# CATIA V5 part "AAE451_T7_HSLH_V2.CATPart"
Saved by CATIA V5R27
Part number: HSLH
Bounding box of the stored display mesh (mm): x -160.298 to 13.7, y -18.483 to 4.512, z -115 to 125
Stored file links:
  W:\AAE 451\AAE451_T7_TailAssembly_V2\AAE451_T7_HSLH_V2.CATPart
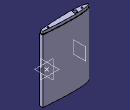
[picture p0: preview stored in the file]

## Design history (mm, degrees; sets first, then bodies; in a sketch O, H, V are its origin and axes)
Set1 "GeometryFromExcel"
  Point1: (1, 0.001, 0)
  Point2: (0.95, 0.0067, 0)
  Point3: (0.9, 0.0121, 0)
  Point4: (0.8, 0.0219, 0)
  Point5: (0.7, 0.0305, 0)
  Point6: (0.6, 0.038, 0)
  Point7: (0.5, 0.0441, 0)
  Point8: (0.4, 0.0484, 0)
  Point9: (0.3, 0.05, 0)
  Point10: (0.25, 0.0495, 0)
  Point11: (0.2, 0.0478, 0)
  Point12: (0.15, 0.0445, 0)
  Point13: (0.1, 0.039, 0)
  Point14: (0.075, 0.035, 0)
  Point15: (0.05, 0.0296, 0)
  Point16: (0.025, 0.0218, 0)
  Point17: (0.0125, 0.0158, 0)
  Point18: (0, 0, 0)
  Point19: (0.0125, -0.0158, 0)
  Point20: (0.025, -0.0218, 0)
  Point21: (0.05, -0.0296, 0)
  Point22: (0.075, -0.035, 0)
  Point23: (0.1, -0.039, 0)
  Point24: (0.15, -0.0445, 0)
  Point25: (0.2, -0.0478, 0)
  Point26: (0.25, -0.0495, 0)
  Point27: (0.3, -0.05, 0)
  Point28: (0.4, -0.0484, 0)
  Point29: (0.5, -0.0441, 0)
  Point30: (0.6, -0.038, 0)
  Point31: (0.7, -0.0305, 0)
  Point32: (0.8, -0.0219, 0)
  Point33: (0.9, -0.0121, 0)
  Point34: (0.95, -0.0067, 0)
  Point35: (1, -0.001, 0)
  Point36: (1, 0.001, 0)
  Point37: (0.95, 0.0067, 0)
  Point38: (0.9, 0.0121, 0)
  Point39: (0.8, 0.0219, 0)
  Point40: (0.7, 0.0305, 0)
  Point41: (0.6, 0.038, 0)
  Point42: (0.5, 0.0441, 0)
  Point43: (0.4, 0.0484, 0)
  Point44: (0.3, 0.05, 0)
  Point45: (0.25, 0.0495, 0)
  Point46: (0.2, 0.0478, 0)
  Point47: (0.15, 0.0445, 0)
  Point48: (0.1, 0.039, 0)
  Point49: (0.075, 0.035, 0)
  Point50: (0.05, 0.0296, 0)
  Point51: (0.025, 0.0218, 0)
  Point52: (0.0125, 0.0158, 0)
  Point53: (0, 0, 0)
  Point54: (0.0125, -0.0158, 0)
  Point55: (0.025, -0.0218, 0)
  Point56: (0.05, -0.0296, 0)
  Point57: (0.075, -0.035, 0)
  Point58: (0.1, -0.039, 0)
  Point59: (0.15, -0.0445, 0)
  Point60: (0.2, -0.0478, 0)
  Point61: (0.25, -0.0495, 0)
  Point62: (0.3, -0.05, 0)
  Point63: (0.4, -0.0484, 0)
  Point64: (0.5, -0.0441, 0)
  Point65: (0.6, -0.038, 0)
  Point66: (0.7, -0.0305, 0)
  Point67: (0.8, -0.0219, 0)
  Point68: (0.9, -0.0121, 0)
  Point69: (0.95, -0.0067, 0)
  Point70: (1, -0.001, 0)
  Curve1: Elements (Point36; Point37; Point38; Point39; Point40; Point41; Point42; Point43; Point44; Point45; Point46; Point47; Point48; Point49; Point50; Point51; Point52; Point53; Point54; Point55; Point56; Point57; Point58; Point59; Point60; Point61; Point62; Point63; Point64; Point65; Point66; Point67; Point68; Point69; Point70)
  Sketch1 on xy-plane, origin (0, 0, 0), H (1, 0, 0), V (0, 1, 0)
    projected curve E1 from edge of Curve1
    point P1 (1, 0.0011)
    line L1 (1, 0.0011) -> (1, -0.001)
    point P3 (1, 0.001)
    point P4 (1, -0.001)
    reference projected point E2 (1, 0.001) from Point1
    reference projected point E3 (1, -0.001) from Point35
    coincidence: P3 E2, P4 E3, P1 P3
Body1 (main body)
  Pad1: profile Sketch1, direction (0, 0, 1), length 1.5215, mirrored extent
  Scaling1: ToTransfor Pad1, Reference Point40, Ratio 230
  Sketch2 on zx-plane, origin (0, 0, 0), H (-1, 0, 0), V (0, 0, 1)
    line L1 (-74.5369, 349.945) -> (165.4631, 349.945)
    line L2 (165.4631, 349.945) -> (165.4631, 115)
    line L3 (165.4631, 115) -> (-74.5369, 115)
    line L4 (-74.5369, 115) -> (-74.5369, 349.945)
    line L5 (-74.5369, -115) -> (165.4631, -115)
    line L6 (165.4631, -115) -> (165.4631, -349.945)
    line L7 (165.4631, -349.945) -> (-74.5369, -349.945)
    line L8 (-74.5369, -349.945) -> (-74.5369, -115)
    reference projected line E1 (-69.7, 349.945) -> (160.3, 349.945) from edge [face of Pad1 from Sketch1.E1 | end face of Pad1]
    reference projected line E2 (-69.7, -349.945) -> (160.3, -349.945) from edge [start face of Pad1 | face of Pad1 from Sketch1.E1]
    distance L3 L5 = 230
    distance L2 L4 = 240
    horizontal: L1 H, L3 H, L5 H, L7 H
    vertical: L2 V, L4 V, L6 V, L8 V
    symmetry: L3 L5 H, L8 L4 H, L2 L6 H
    coincidence: L1 E1, L7 E2
  Pocket1: profile Sketch2, direction (0, -1, 0), through (limit type 6), opposite side through (limit type 6)
  Sketch3 on face of Pocket1 from Sketch2.L3, origin (0, 0, 115), H (1, 0, 0), V (0, 1, 0)
    line L1 (13.7, -12.9188) -> (13.7, -1.064)
    point P1 (13.7, -12.9188)
    point P2 (13.7, -1.064)
    reference projected curve E1 from edge [face of Pad1 from Sketch1.E1 | face of Pocket1 from Sketch2.L3]
    reference projected curve E2 from edge [face of Pad1 from Sketch1.E1 | face of Pocket1 from Sketch2.L3]
    projected curve E3 from edge [face of Pad1 from Sketch1.E1 | face of Pocket1 from Sketch2.L3]
    projected curve E4 from edge [face of Pad1 from Sketch1.E1 | face of Pocket1 from Sketch2.L3]
    projected curve E5 from edge [face of Pad1 from Sketch1.E1 | face of Pocket1 from Sketch2.L3]
    point P3 (69.7, -6.7499)
    line L2 (69.7, -6.7499) -> (69.7, -7.2329)
    distance L1 P3 = 56
    coincidence: P1 E1, P2 E2
    vertical: L1 V
  Pocket2: profile Sketch3, direction (0, 0, -1), through (limit type 6)
  Shell1: ExtOffset 0, Face (face of Pocket1 from Sketch2.L3; face of Pocket1 from Sketch2.L5), IntOffset 1.8
  Sketch4 on face of Pocket1 from Sketch2.L3, origin (0, 0, 115), H (1, 0, 0), V (0, 1, 0)
    projected curve E1 from edge [face of Shell1 | face of Pocket1 from Sketch2.L3]
    projected line E2 (11.9, -11.2688) -> (11.9, -2.714) from edge [face of Pocket1 from Sketch2.L3 | face of Shell1]
  Pad2: profile Sketch4, direction (0, 0, 1), length 10, opposite side length 10
  Plane1: type Offset, RefPlane yz-plane, Offset 120, reversed
  Sketch5 on xy-plane, origin (0, 0, 0), H (1, 0, 0), V (0, 1, 0)
    circle A1 centre (-110, -7) radius 6.85
    point P1 (-110, -7)
    reference intersected line E1 through (-120, 0) direction (0, 1) from Plane1
    radius A1 = 6.85
    distance P1 H = 7
    distance E1 P1 = 10
  Pocket3: profile Sketch5, direction (0, 0, -1), through (limit type 6), opposite side through (limit type 6)
  Sketch6 on face of Pocket1 from Sketch2.L3, origin (0, 0, 115), H (1, 0, 0), V (0, 1, 0)
    projected circle E1 centre (-110, -7) radius 6.85 from edge [end face of Pad2 | face of Pocket3 from Sketch5.A1]
    circle A1 centre (-110, -7) radius 10
    radius A1 = 10
    concentricity: A1 E1
  Pad3: profile Sketch6, direction (0, 0, -1), length 220
  Sketch7 on end face of Pad2, origin (0, 0, 125), H (1, 0, 0), V (0, 1, 0)
    circle A1 centre (-135, -6) radius 2.972
    point P1 (-135, -6)
    radius A1 = 2.972
    distance H P1 = 6
    distance P1 V = 135
  Pocket4: profile Sketch7, direction (0, 0, -1), length 7.92
  RectPattern1: of Pocket4, direction 1 instances 2, spacing 125, along end face of Pad2
  Sketch8 on face of Pocket2 from Sketch3.L1, origin (13.7, 0, 0), H (0, 1, 0), V (0, 0, 1)
    line L1 (-7.4914, 8) -> (-6.4914, 8)
    line L2 (-6.4914, 8) -> (-6.4914, -8)
    line L3 (-6.4914, -8) -> (-7.4914, -8)
    line L4 (-7.4914, -8) -> (-7.4914, 8)
    construction line L5 (-6.9914, 14.8043) -> (-6.9914, -16.204)
    reference projected line E1 (-12.9188, 115) -> (-12.9188, -115) from edge [face of Pad1 from Sketch1.E1 | face of Pocket2 from Sketch3.L1]
    reference projected line E2 (-1.064, 115) -> (-1.064, -115) from edge [face of Pocket2 from Sketch3.L1 | face of Pad1 from Sketch1.E1]
    length L1 = 1
    length L2 = 16
    horizontal: L1 H, L3 H
    vertical: L2 V, L4 V
    symmetry: L1 L3 H, L4 L2 L5, E1 E2 L5
  Pocket5: profile Sketch8, direction (-1, 0, 0), length 13.7
  Sketch9 on face of Pocket2 from Sketch3.L1, origin (13.7, 0, 0), H (0, 1, 0), V (0, 0, 1)
    projected line E1 (-7.4914, 8) -> (-7.4914, -8) from edge [face of Pocket2 from Sketch3.L1 | face of Pocket5 from Sketch8.L4]
    point P2 (-7.4914, -8)
    projected line E2 (-6.4914, -8) -> (-6.4914, 8) from edge [face of Pocket2 from Sketch3.L1 | face of Pocket5 from Sketch8.L2]
    projected line E3 (-6.4914, 8) -> (-7.4914, 8) from edge [face of Pocket2 from Sketch3.L1 | face of Pocket5 from Sketch8.L1]
    projected line E4 (-7.4914, -8) -> (-6.4914, -8) from edge [face of Pocket2 from Sketch3.L1 | face of Pocket5 from Sketch8.L3]
    line L1 (-8.4914, 9) -> (-5.4914, 9)
    line L2 (-5.4914, 9) -> (-5.4914, -9)
    line L3 (-5.4914, -9) -> (-8.4914, -9)
    line L4 (-8.4914, -9) -> (-8.4914, 9)
    distance L4 E1 = 1
    distance E3 L1 = 1
    distance E2 L2 = 1
    distance L3 P2 = 1
    horizontal: L1 H, L3 H
    vertical: L2 V, L4 V
  Pad4: profile Sketch9, direction (-1, 0, 0), length 13.7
